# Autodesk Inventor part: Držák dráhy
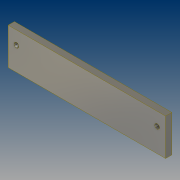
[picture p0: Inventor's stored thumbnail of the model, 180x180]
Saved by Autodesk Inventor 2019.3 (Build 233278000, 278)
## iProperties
Created: 2019-03
Part Number: Držák dráhy
Material: Ocel, měkká, svařovaná
Document SubType Name: Modeling
Designer: B-hon
Density: 7.85 g/cm^3
Appearance: Stříbro
Author: B-hon
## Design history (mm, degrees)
sketch "Náčrt1"
  geometry: L1 (0, 0)-(150, 0); L2 (150, 0)-(150, 35); L3 (150, 35)-(0, 35); L4 (0, 35)-(0, 0)
  constraints: 8 end point, 2 parallel, 1 horizontal, 1 perpendicular
  dimensions: "d0" = 150 distance of L3.end L2.end; "d1" = 35 distance of L2.end L1.end
extrude "Vysunutí1" new body sketch "Náčrt1" distance "d2" = 6; taper "d3" = 0 deg
sketch "Náčrt3"
  geometry: L1 (0, 35)-(0, 0) reference; L2 (0, 0)-(150, 0) reference; 2 further points
  constraints: 1 horizontal alignment
  dimensions: "d15" = 134 distance of point (142, 22.5) point (8, 22.5); "d16" = 8 distance from line of L1 point (8, 22.5); "d17" = 22.5 distance from line of L2 point (8, 22.5)
hole "Díra1" sketch "Náčrt3" at (8, 22.5), (142, 22.5) diameter "d18" = 4.5; stored, may be unused: countersink angle "d22" = 90 deg, drill point angle "d24" = 118 deg; dims "d19" = 6, "d20" = 11, "d21" = 8, "d23" = 8
node "Těleso1"
